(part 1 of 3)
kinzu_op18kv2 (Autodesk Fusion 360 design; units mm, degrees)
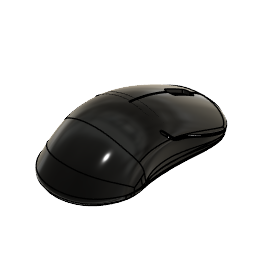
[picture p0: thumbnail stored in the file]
parameter "d11" = 0.5
parameter "d441" = 0.2
place_component sketch "スケッチ1"
sketch "スケッチ1" plane through (0, 0, 0) normal (0, 0, 1) x axis (1, 0, 0)
  line L1 (-100, -100) -> (100, -100)
  line L2 (-100, 100) -> (-100, -100)
  line L3 (100, 100) -> (-100, 100)
  line L4 (100, -100) -> (100, 100)
  line L5 (-100, 100) -> (100, -100)
  line L6 (100, 100) -> (-100, -100)
  point P6 (0, 0)
  point P1 (0, 0)
  point P4 (-100, 100)
  point P5 (100, 100)
  point P3 (-100, -100)
  horizontal L1
  perpendicular L1 L2
  parallel L1 L3
  parallel L2 L4
  coincident L5 P6
  coincident L6 P6
  coincident P1 P6
  dimension "d13" distance P4 P5 = 200
  dimension "d14" distance P3 P4 = 200
extrude "押し出し1" new body sketch "スケッチ1" profile of L1 L2 L3 L4 against normal blind 5
sketch "スケッチ1" plane through (0, 0, 0) normal (0, 0, 1) x axis (1, 0, 0)
  line L1 (2, 0) -> (-2, 0)
  line L2 (2, -4) -> (2, 0)
  line L3 (-2, -4) -> (2, -4)
  line L4 (-2, 0) -> (-2, -4)
  line L5 (0, -7.68) -> (0, 0)
  line L6 (4.05, 8.27) -> (-4.05, 8.27)
  line L7 (4.05, -7.68) -> (4.05, 8.27)
  line L8 (-4.05, -7.68) -> (4.05, -7.68)
  line L9 (-4.05, 8.27) -> (-4.05, -7.68)
  arc A1 centre (0, 0) radius 2 clockwise from (-2, 0) to (2, 0)
  point P7 (0, -7.68)
  point P6 (0, 0)
  point P12 (0, 0)
  point P2 (-2, 0)
  point P3 (2, 0)
  point P5 (-2, -4)
  point P8 (-4.05, 8.27)
  point P9 (4.05, 8.27)
  point P11 (-4.05, -7.68)
  horizontal L1
  vertical L2
  horizontal L3
  vertical L4
  perpendicular L3 L5
  horizontal L6
  vertical L7
  horizontal L8
  vertical L9
  midpoint P7 L8
  coincident P6 P12
  dimension "d2" distance P2 P3 = 4
  dimension "d3" distance P2 P5 = 4
  dimension "d4" distance P6 P7 = 7.68
  dimension "d5" distance P8 P9 = 8.1
  dimension "d6" distance P8 P11 = 15.95
  dimension "d21" radius A1 = 2
extrude "押し出し2" new body sketch "スケッチ1" profile of L1 L2 L3 L4 L5 A1 along normal blind 2.4 taper 22.5 bodies "lens"
extrude "押し出し5" add sketch "スケッチ1" to an object from offset 7.4
sketch "スケッチ1" plane through (0, 0, 0) normal (0, 0, 1) x axis (1, 0, 0)
  line L1 (-10, -10) -> (10, -10)
  line L2 (-10, 10) -> (-10, -10)
  line L3 (10, 10) -> (-10, 10)
  line L4 (10, -10) -> (10, 10)
  line L5 (-10, 10) -> (10, -10)
  line L6 (10, 10) -> (-10, -10)
  line L7 (2, -4) -> (2, 0)
  line L8 (-2, -4) -> (2, -4)
  line L9 (-2, 0) -> (-2, -4)
  line L10 (3.5, -4.5) -> (3.5, 0)
  line L11 (-2.5, -5.5) -> (2.5, -5.5)
  line L12 (-3.5, 0) -> (-3.5, -4.5)
  line L13 (-6.5, 0) -> (-6.5, -4.5)
  line L14 (6.5, -4.5) -> (6.5, 0)
  line L15 (-2.5, -8.5) -> (2.5, -8.5)
  arc A1 centre (0, 0) radius 2 clockwise from (-2, 0) to (2, 0)
  arc A2 centre (0, 0) radius 3.5 clockwise from (-3.5, 0) to (3.5, 0)
  arc A3 centre (-2.5, -4.5) radius 1 clockwise from (-2.5, -5.5) to (-3.5, -4.5)
  arc A4 centre (2.5, -4.5) radius 1 clockwise from (3.5, -4.5) to (2.5, -5.5)
  arc A5 centre (0, 0) radius 6.5 clockwise from (-6.5, 0) to (6.5, 0)
  arc A6 centre (2.5, -4.5) radius 4 clockwise from (6.5, -4.5) to (2.5, -8.5)
  arc A7 centre (-2.5, -4.5) radius 4 clockwise from (-2.5, -8.5) to (-6.5, -4.5)
  point P6 (0, 0)
  point P1 (0, 0)
  point P7 (0, 0)
  point P4 (-10, 10)
  point P5 (10, 10)
  point P3 (-10, -10)
  point P9 (-2, 0)
  point P10 (2, 0)
  point P12 (-2, -4)
  horizontal L1
  perpendicular L1 L2
  parallel L1 L3
  parallel L2 L4
  coincident L5 P6
  coincident L6 P6
  coincident P1 P6
  coincident P1 P7
  vertical L7
  horizontal L8
  vertical L9
  concentric A1 A2
  tangent L12 A2
  tangent L12 A3
  tangent L11 A3
  tangent L10 A4
  tangent L11 A4
  equal A3 A4
  dimension "d29" distance P4 P5 = 20
  dimension "d30" distance P3 P4 = 20
  dimension "d40" radius A1 = 2
  dimension "d41" distance P9 P10 = 4
  dimension "d42" distance P9 P12 = 4
  dimension "d44" radius A3 = 1
  dimension "d45" = 3
extrude "押し出し2" sketch "スケッチ1" profile of L1 L2 L3 L4 A1 L7 L8 L9 L10 L11 L12 A2 A3 A4 L13 A7 L14 A5 A6 L15 to an object offset 0.5 from offset -0.5 bodies "around_lens"
extrude "押し出し3" cut sketch "スケッチ1" profile of L10 L11 L12 A2 A3 A4 L13 A7 L14 A5 A6 L15 along normal blind 0.7
combine "結合2"
sketch "スケッチ1" plane through (0, 0, 0) normal (0, 0, 1) x axis (1, 0, 0)
  line L1 (0, -15) -> (0, 15)
  line L2 (-5.25, -15) -> (-5.25, 15)
  line L3 (5.25, -15) -> (5.25, 15)
  line L4 (-4.3, -15) -> (-4.3, 15)
  line L5 (4.3, -15) -> (4.3, 15)
  line L6 (10, 0) -> (-10, 0)
  line L7 (10, -8.44) -> (-10, -8.44)
  line L8 (10, 8.82) -> (-10, 8.82)
  line L9 (10, -5.66) -> (-10, -5.66)
  line L10 (10, 6.8) -> (-10, 6.8)
  line L11 (10, 7.69) -> (-10, 7.69)
  line L12 (10, -4.77) -> (-10, -4.77)
  line L13 (5.45, -15) -> (5.45, 15)
  line L14 (-5.45, -15) -> (-5.45, 15)
  line L15 (10, 7.94) -> (-10, 7.94)
  line L16 (10, 7.05) -> (-10, 7.05)
  line L17 (10, -5.02) -> (-10, -5.02)
  line L18 (10, -5.91) -> (-10, -5.91)
  point P1 (0, 0)
  vertical L1
  midpoint P1 L1
  perpendicular L2 L6
  midpoint P1 L6
  dimension "d91" = 5.25
  dimension "d92" = -5.25
  dimension "d93" = 4.3
  dimension "d94" = -4.3
  dimension "d95" = 8.44
  dimension "d96" = -8.82
  dimension "d97" = 5.66
  dimension "d102" = -12.46 (= "( -1.78 * 7 ) * 1 mm")
  dimension "d103" = -0.89
  dimension "d104" = -0.89
  dimension "d105" = -0.2
  dimension "d106" = 0.2
  dimension "d107" = -0.25
  dimension "d108" = -0.25
  dimension "d109" = 0.25
  dimension "d110" = 0.25
extrude "押し出し1" new body sketch "スケッチ1" profile of L1 L4 L5 L6 L7 L8 L9 L10 L11 L12 L15 L16 L17 L18 to an object offset 7.4 from offset 9.81 bodies "sensor"
extrude "押し出し2" sketch "スケッチ1" profile of L2 L3 L4 L5 L6 L9 L10 L11 L12 L13 L14 L15 L16 L17 L18 blind -0.2 from offset -0.5
extrude "押し出し3" sketch "スケッチ1" profile of L2 L3 L6 L9 L10 L11 L12 L13 L14 L15 L16 L17 L18 blind -4.51 from offset -0.5
sketch "スケッチ1" plane through (0, 0, 0) normal (0, 0, 1) x axis (1, 0, 0)
  line L1 (0, 15.4) -> (0, 0)
  line L2 (0, -14.4) -> (0, 0)
  line L3 (-4.3, 0) -> (4.3, 0)
  line L4 (-4.3, 8.82) -> (4.3, 8.82)
  line L5 (-4.3, -8.44) -> (4.3, -8.44)
  line L6 (4.3, 8.82) -> (4.3, -8.44)
  line L7 (-4.3, 8.82) -> (-4.3, -8.44)
  line L8 (12, 15.4) -> (0, 15.4)
  line L9 (-12.8, 15.4) -> (0, 15.4)
  line L10 (0, -31.8) -> (0, 0)
  circle C1 centre (12, 15.4) radius 1.4
  circle C2 centre (-12.8, 15.4) radius 1.4
  circle C3 centre (0, -14.4) radius 1.4
  circle C4 centre (0, -31.8) radius 1.4
  point P1 (0, 0)
  point P2 (0, 0)
  point P6 (0, 0)
  point P7 (0, -14.4)
  point P8 (0, -14.4)
  point P4 (12, 15.4)
  point P16 (12, 15.4)
  point P5 (-12.8, 15.4)
  point P17 (-12.8, 15.4)
  point P18 (0, 0)
  point P9 (0, -31.8)
  point P19 (0, -31.8)
  point P3 (0, 15.4)
  point P10 (4.3, 0)
  point P11 (-4.3, 0)
  coincident P1 P2
  vertical L1
  coincident P1 P6
  coincident P7 P8
  perpendicular L2 L3
  midpoint P6 L3
  perpendicular L4 L6
  perpendicular L4 L7
  perpendicular L1 L8
  perpendicular L1 L9
  coincident P4 P16
  coincident P5 P17
  coincident P1 P18
  perpendicular L3 L10
  coincident P9 P19
  dimension "d51" distance P2 P3 = 15.4
  dimension "d53" diameter C1 = 2.8
  dimension "d54" diameter C2 = 2.8
  dimension "d56" distance P6 P7 = 14.4
  dimension "d57" diameter C3 = 2.8
  dimension "d58" diameter C4 = 2.8
  dimension "d120" distance P10 P11 = 8.6
  dimension "d121" = 8.82
  dimension "d122" = -8.44
  dimension "d187" distance P3 P16 = 12
  dimension "d188" distance P3 P17 = 12.8
  dimension "d189" distance P18 P19 = 31.8
sketch "スケッチ2" plane through (0, 0, 0) normal (0, 0, 1) x axis (1, 0, 0)
  line L1 (50, 0) -> (-50, 0)
  line L2 (0, -50) -> (0, 50)
  line L3 (-13.8, -50) -> (-13.8, 50)
  line L4 (14, -50) -> (14, 50)
  line L5 (50, 39.3) -> (-50, 39.3)
  line L6 (50, -12.8) -> (-50, -12.8)
  line L7 (50, -33.6) -> (-50, -33.6)
  line L8 (-2.3, -50) -> (-2.3, 50)
  line L9 (2.3, -50) -> (2.3, 50)
  line L10 (7.3, -50) -> (7.3, 50)
  line L11 (50, -28.4) -> (-50, -28.4)
  line L12 (50, -9.7) -> (-50, -9.7)
  line L13 (-10.1, -50) -> (-10.1, 50)
  line L14 (9.3, -50) -> (9.3, 50)
  line L15 (50, -7.7) -> (-50, -7.7)
  line L16 (50, 36.5) -> (-50, 36.5)
  line L17 (-7.3, 39.3) -> (-10.1, 36.5)
  line L18 (10.6, -50) -> (10.6, 50)
  line L19 (14, 20.0176) -> (10.6, 39.3)
  point P1 (0, 0)
  point P34 (-10.1, 36.5)
  point P35 (-7.3, 39.3)
  point P38 (10.6, 39.3)
  point P39 (14, 20.0176)
  horizontal L1
  midpoint P1 L1
  vertical L2
  midpoint P1 L2
  coincident L13 P34
  coincident L16 P34
  coincident L5 P35
  coincident L18 P38
  coincident L5 P38
  coincident L4 P39
  dimension "d73" = 13.8
  dimension "d74" = -14
  dimension "d75" = -39.3
  dimension "d76" = 12.8
  dimension "d77" = 20.8
  dimension "d78" = 2.3
  dimension "d79" = -2.3
  dimension "d80" = -5
  dimension "d81" = -5.2
  dimension "d82" = -3.1
  dimension "d83" = -3.7
  dimension "d205" = 4.7
  dimension "d206" = -5.1
  dimension "d211" = -36.5
  dimension "d212" angle L5 L17 = 45
  dimension "d214" = 3.4
  dimension "d416" angle L5 L19 = 80
sketch "スケッチ3" plane through (0, 0, 0) normal (0, 0, 1) x axis (1, 0, 0)
  line L1 (25, 0) -> (-25, 0)
  line L2 (25, 22.2) -> (-25, 22.2)
  line L3 (25, 37.6) -> (-25, 37.6)
  line L4 (0, 50.6) -> (0, 0)
  line L5 (6.8, 50.6) -> (6.8, 0.6)
  line L6 (-6.8, 50.6) -> (-6.8, 0.6)
  line L7 (25, 36) -> (-25, 36)
  line L8 (25, 34.2) -> (-25, 34.2)
  line L9 (25, 23.1) -> (-25, 23.1)
  line L10 (25, 24.9) -> (-25, 24.9)
  line L11 (7.6, 50.6) -> (7.6, 0.6)
  line L12 (-7.6, 50.6) -> (-7.6, 0.6)
  circle C1 centre (-4.8, 35.6) radius 2
  circle C2 centre (-5.3, 23.7) radius 1.5
  circle C3 centre (5.6, 35.6) radius 2
  circle C4 centre (4.8, 24.2) radius 2
  point P1 (0, 0)
  point P8 (0, 0)
  horizontal L1
  coincident P1 P8
  perpendicular L3 L4
  tangent L6 C1
  tangent L3 C1
  tangent L2 C2
  tangent L6 C2
  tangent L3 C3
  tangent L11 C3
  tangent L5 C4
  tangent L2 C4
  dimension "d156" = -22.2
  dimension "d157" = -15.4
  dimension "d158" = 6.8
  dimension "d159" = -6.8
  dimension "d169" = 1.6
  dimension "d170" = 1.8
  dimension "d171" = -0.9
  dimension "d172" = -1.8
  dimension "d174" = 0.8
  dimension "d175" radius C1 = 2
  dimension "d176" radius C2 = 1.5
  dimension "d177" = -0.8
  dimension "d178" radius C3 = 2
  dimension "d179" radius C4 = 2
extrude "押し出し1" new body sketch "スケッチ2" blind -0.8 from offset 7.4 bodies "main_pcb"
extrude "押し出し2" cut sketch "スケッチ1" profile of L1 C1 C2 L2 C3 C4 L3 L4 L5 L6 L7 to an object
extrude "押し出し3" sketch "スケッチ3" profile of L2 L3 L4 L5 L6 L7 L8 L9 L10 L11 C1 C2 L12 C3 C4 to an object
sketch "スケッチ5" plane through (0, 0, 0) normal (0, 0, 1) x axis (1, 0, 0)
  line L1 (-12.25, 0) -> (0, 0)
  line L2 (-12.25, -5.5) -> (-12.25, 0)
  line L3 (0, -5.5) -> (-12.25, -5.5)
  line L4 (0, 0) -> (0, -5.5)
  line L5 (-11.45, 0) -> (0, 0)
  line L6 (-11.45, 9.05) -> (-11.45, 0)
  line L7 (0, 9.05) -> (-11.45, 9.05)
  line L8 (0, 0) -> (0, 9.05)
  line L9 (10.7, 0) -> (0, 0)
  line L10 (10.7, -2.8) -> (10.7, 0)
  line L11 (0, -2.8) -> (10.7, -2.8)
  line L12 (0, 0) -> (0, -2.8)
  line L13 (12.2, 0) -> (0, 0)
  line L14 (12.2, 9.05) -> (12.2, 0)
  line L15 (0, 9.05) -> (12.2, 9.05)
  line L16 (0, 0) -> (0, 9.05)
  line L17 (-12.5, -7.75) -> (-12.5, -3.25)
  line L18 (-12, -3.25) -> (-12, -7.75)
  line L19 (-12.25, -7.75) -> (-12.25, -3.25)
  line L20 (10.45, -5.8) -> (10.45, 0.2)
  line L21 (10.95, 0.2) -> (10.95, -5.8)
  line L22 (10.7, -5.8) -> (10.7, 0.2)
  line L23 (11.95, 7.55) -> (11.95, 10.55)
  line L24 (12.45, 10.55) -> (12.45, 7.55)
  line L25 (12.2, 7.55) -> (12.2, 10.55)
  line L26 (-11.7, 7.55) -> (-11.7, 10.55)
  line L27 (-11.2, 10.55) -> (-11.2, 7.55)
  line L28 (-11.45, 7.55) -> (-11.45, 10.55)
  line L29 (-13.8, -9.25) -> (-10.2, -9.25)
  line L30 (-13.8, -1.75) -> (-13.8, -9.25)
  line L31 (-10.2, -1.75) -> (-13.8, -1.75)
  line L32 (-10.2, -9.25) -> (-10.2, -1.75)
  line L33 (-13.8, -1.75) -> (-10.2, -9.25)
  line L34 (-10.2, -1.75) -> (-13.8, -9.25)
  line L35 (-13.5, 6.05) -> (-9.9, 6.05)
  line L36 (-13.5, 12.05) -> (-13.5, 6.05)
  line L37 (-9.9, 12.05) -> (-13.5, 12.05)
  line L38 (-9.9, 6.05) -> (-9.9, 12.05)
  line L39 (-13.5, 12.05) -> (-9.9, 6.05)
  line L40 (-9.9, 12.05) -> (-13.5, 6.05)
  line L41 (10.15, 6.05) -> (13.75, 6.05)
  line L42 (10.15, 12.05) -> (10.15, 6.05)
  line L43 (13.75, 12.05) -> (10.15, 12.05)
  line L44 (13.75, 6.05) -> (13.75, 12.05)
  line L45 (10.15, 12.05) -> (13.75, 6.05)
  line L46 (13.75, 12.05) -> (10.15, 6.05)
  line L47 (15.45, 1.7) -> (10.45, 1.7)
  line L48 (15.45, -7.3) -> (15.45, 1.7)
  line L49 (10.45, -7.3) -> (15.45, -7.3)
  line L50 (10.45, 1.7) -> (10.45, -7.3)
  line L51 (-12.95, 0) -> (0, 0)
  line L52 (-12.95, 20.2) -> (-12.95, 0)
  line L53 (0, 20.2) -> (-12.95, 20.2)
  line L54 (0, 0) -> (0, 20.2)
  line L55 (-11.9, 19.15) -> (-14, 19.15)
  line L56 (-11.9, 21.25) -> (-11.9, 19.15)
  line L57 (-14, 21.25) -> (-11.9, 21.25)
  line L58 (-14, 19.15) -> (-14, 21.25)
  line L59 (-11.9, 21.25) -> (-14, 19.15)
  line L60 (-14, 21.25) -> (-11.9, 19.15)
  line L61 (5.35, 0) -> (0, 0)
  line L62 (5.35, -24.1) -> (5.35, 0)
  line L63 (0, -24.1) -> (5.35, -24.1)
  line L64 (0, 0) -> (0, -24.1)
  line L65 (3.65, -25.8) -> (7.05, -25.8)
  line L66 (3.65, -22.4) -> (3.65, -25.8)
  line L67 (7.05, -22.4) -> (3.65, -22.4)
  line L68 (7.05, -25.8) -> (7.05, -22.4)
  line L69 (3.65, -22.4) -> (7.05, -25.8)
  line L70 (7.05, -22.4) -> (3.65, -25.8)
  line L71 (5.263, 34.1334) -> (10.2639, 35.0265)
  line L72 (7.5133, 21.5328) -> (5.263, 34.1334)
  line L73 (12.5142, 22.4259) -> (7.5133, 21.5328)
  line L74 (10.2639, 35.0265) -> (12.5142, 22.4259)
  line L75 (7.5133, 21.5328) -> (10.2639, 35.0265)
  line L76 (12.5142, 22.4259) -> (5.263, 34.1334)
  line L77 (8.0065, 33.2824) -> (9.7707, 23.2768)
  line L78 (8.55, 30.2) -> (8.8886, 28.2796)
  line L79 (7.2262, 29.3573) -> (10.0822, 29.8609)
  line L80 (7.0178, 30.5391) -> (7.2262, 29.3573)
  line L81 (9.8738, 31.0427) -> (7.0178, 30.5391)
  line L82 (10.0822, 29.8609) -> (9.8738, 31.0427)
  line L83 (7.0178, 30.5391) -> (10.0822, 29.8609)
  line L84 (9.8738, 31.0427) -> (7.2262, 29.3573)
  line L85 (9.6519, 22.7989) -> (10.0458, 22.8684)
  line L86 (7.7314, 33.6909) -> (9.6519, 22.7989)
  line L87 (8.1253, 33.7603) -> (7.7314, 33.6909)
  line L88 (10.0458, 22.8684) -> (8.1253, 33.7603)
  line L89 (7.7314, 33.6909) -> (10.0458, 22.8684)
  line L90 (8.1253, 33.7603) -> (9.6519, 22.7989)
  line L91 (8.55, 0) -> (0, 0)
  line L92 (8.55, 30.2) -> (8.55, 0)
  line L93 (0, 30.2) -> (8.55, 30.2)
  line L94 (0, 0) -> (0, 30.2)
  arc A1 centre (-12.25, -7.75) radius 0.25 clockwise from (-12, -7.75) to (-12.5, -7.75)
  arc A2 centre (-12.25, -3.25) radius 0.25 clockwise from (-12.5, -3.25) to (-12, -3.25)
  arc A3 centre (10.7, -5.8) radius 0.25 clockwise from (10.95, -5.8) to (10.45, -5.8)
  arc A4 centre (10.7, 0.2) radius 0.25 clockwise from (10.45, 0.2) to (10.95, 0.2)
  arc A5 centre (12.2, 7.55) radius 0.25 clockwise from (12.45, 7.55) to (11.95, 7.55)
  arc A6 centre (12.2, 10.55) radius 0.25 clockwise from (11.95, 10.55) to (12.45, 10.55)
  arc A7 centre (-11.45, 7.55) radius 0.25 clockwise from (-11.2, 7.55) to (-11.7, 7.55)
  arc A8 centre (-11.45, 10.55) radius 0.25 clockwise from (-11.7, 10.55) to (-11.2, 10.55)
  circle C1 centre (5.35, -24.1) radius 0.85
  point P1 (0, 0)
  point P2 (0, 0)
  point P6 (0, 0)
  point P10 (0, 0)
  point P14 (0, 0)
  point P4 (-12.25, -5.5)
  point P24 (-12.25, -5.5)
  point P12 (10.7, -2.8)
  point P31 (10.7, -2.8)
  point P16 (12.2, 9.05)
  point P38 (12.2, 9.05)
  point P8 (-11.45, 9.05)
  point P45 (-11.45, 9.05)
  point P50 (-12, -5.5)
  point P55 (-11.7, 9.05)
  point P60 (11.95, 9.05)
  point P65 (0, 0)
  point P73 (-12.95, 20.2)
  point P67 (-12.95, 20.2)
  point P74 (0, 0)
  point P82 (5.35, -24.1)
  point P76 (5.35, -24.1)
  point P83 (5.35, -24.1)
  point P88 (8.8886, 28.2796)
  point P91 (8.8886, 28.2796)
  point P92 (8.8886, 28.2796)
  point P98 (8.55, 30.2)
  point P93 (8.55, 30.2)
  point P103 (8.8886, 28.2796)
  point P104 (0, 0)
  point P106 (8.55, 30.2)
  point P3 (-12.25, 0)
  point P5 (0, -5.5)
  point P7 (-11.45, 0)
  point P9 (0, 9.05)
  point P11 (10.7, 0)
  point P13 (0, -2.8)
  point P15 (12.2, 0)
  point P17 (0, 9.05)
  point P48 (-13.8, -1.75)
  point P49 (-10.2, -1.75)
  point P47 (-13.8, -9.25)
  point P53 (-13.5, 12.05)
  point P54 (-9.9, 12.05)
  point P52 (-13.5, 6.05)
  point P58 (10.15, 12.05)
  point P59 (13.75, 12.05)
  point P57 (10.15, 6.05)
  point P61 (10.45, 1.7)
  point P62 (15.45, 1.7)
  point P64 (10.45, -7.3)
  point P66 (-12.95, 0)
  point P68 (0, 20.2)
  point P71 (-11.9, 21.25)
  point P72 (-14, 21.25)
  point P70 (-11.9, 19.15)
  point P75 (5.35, 0)
  point P77 (0, -24.1)
  point P80 (3.65, -22.4)
  point P81 (7.05, -22.4)
  point P79 (3.65, -25.8)
  point P86 (7.5133, 21.5328)
  point P87 (12.5142, 22.4259)
  point P85 (5.263, 34.1334)
  point P90 (8.0065, 33.2824)
  point P96 (7.0178, 30.5391)
  point P97 (9.8738, 31.0427)
  point P95 (7.2262, 29.3573)
  point P101 (7.7314, 33.6909)
  point P102 (8.1253, 33.7603)
  point P100 (9.6519, 22.7989)
  point P105 (8.55, 0)
  point P107 (0, 30.2)
  horizontal L1
  vertical L2
  horizontal L3
  vertical L4
  coincident P1 P2
  horizontal L5
  vertical L6
  horizontal L7
  vertical L8
  coincident P1 P6
  horizontal L9
  vertical L10
  horizontal L11
  vertical L12
  coincident P1 P10
  horizontal L13
  vertical L14
  horizontal L15
  vertical L16
  coincident P1 P14
  tangent L17 A1
  tangent A1 L18
  parallel L17 L18
  tangent L18 A2
  tangent L17 A2
  perpendicular L3 L19
  coincident P4 P24
  midpoint L19 P24
  tangent L20 A3
  tangent A3 L21
  parallel L20 L21
  tangent L21 A4
  tangent L20 A4
  perpendicular L11 L22
  coincident P12 P31
  midpoint L22 P31
  tangent L23 A5
  tangent A5 L24
  parallel L23 L24
  tangent L24 A6
  tangent L23 A6
  perpendicular L15 L25
  coincident P16 P38
  midpoint L25 P38
  tangent L26 A7
  tangent A7 L27
  parallel L26 L27
  tangent L27 A8
  tangent L26 A8
  perpendicular L7 L28
  coincident P8 P45
  midpoint L28 P45
  horizontal L29
  perpendicular L29 L30
  parallel L29 L31
  parallel L30 L32
  coincident L33 P50
  coincident L34 P50
  horizontal L35
  perpendicular L35 L36
  parallel L35 L37
  parallel L36 L38
  coincident L39 P55
  coincident L40 P55
  midpoint L26 P55
  horizontal L41
  perpendicular L41 L42
  parallel L41 L43
  parallel L42 L44
  coincident L45 P60
  coincident L46 P60
  horizontal L47
  vertical L48
  horizontal L49
  vertical L50
  midpoint L20 L50
  midpoint L18 P50
  midpoint L23 P60
  horizontal L51
  vertical L52
  horizontal L53
  vertical L54
  coincident P1 P65
  horizontal L55
  perpendicular L55 L56
  parallel L55 L57
  parallel L56 L58
  coincident L59 P73
  coincident L60 P73
  coincident P67 P73
  horizontal L61
  vertical L62
  horizontal L63
  vertical L64
  coincident P1 P74
  horizontal L65
  perpendicular L65 L66
  parallel L65 L67
  parallel L66 L68
  coincident L69 P82
  coincident L70 P82
  coincident P76 P82
  coincident P82 P83
  perpendicular L71 L72
  parallel L71 L73
  parallel L72 L74
  coincident L75 P88
  coincident L76 P88
  coincident P88 P91
  midpoint L77 P91
  coincident P88 P92
  parallel L77 L78
  perpendicular L79 L80
  parallel L79 L81
  parallel L80 L82
  coincident L83 P98
  coincident L84 P98
  coincident P93 P98
  parallel L77 L82
  perpendicular L85 L86
  parallel L85 L87
  parallel L86 L88
  coincident L89 P103
  coincident L90 P103
  coincident P88 P103
  parallel L77 L88
  horizontal L91
  vertical L92
  horizontal L93
  vertical L94
  coincident P1 P104
  coincident P98 P106
  dimension "d218" distance P2 P3 = 12.25
  dimension "d219" distance P2 P5 = 5.5
  dimension "d220" distance P6 P7 = 11.45
  dimension "d221" distance P6 P9 = 9.05
  dimension "d222" distance P10 P11 = 10.7
  dimension "d223" distance P10 P13 = 2.8
  dimension "d224" distance P14 P15 = 12.2
  dimension "d225" distance P14 P17 = 9.05
  dimension "d226" diameter A1 = 0.5
  dimension "d227" diameter A3 = 0.5
  dimension "d228" diameter A5 = 0.5
  dimension "d229" diameter A7 = 0.5
  dimension "d230" distance P48 P49 = 3.6
  dimension "d231" distance P47 P48 = 7.5
  dimension "d232" distance P53 P54 = 3.6
  dimension "d233" distance P52 P53 = 6
  dimension "d234" distance P58 P59 = 3.6
  dimension "d235" distance P57 P58 = 6
  dimension "d236" distance P61 P62 = 5
  dimension "d237" distance P61 P64 = 9
  dimension "d255" distance P65 P66 = 12.95
  dimension "d256" distance P65 P68 = 20.2
  dimension "d257" distance P71 P72 = 2.1
  dimension "d258" distance P70 P71 = 2.1
  dimension "d259" distance P74 P75 = 5.35
  dimension "d260" distance P74 P77 = 24.1
  dimension "d261" distance P80 P81 = 3.4
  dimension "d262" distance P79 P80 = 3.4
  dimension "d266" diameter C1 = 1.7
  dimension "d276" distance P86 P87 = 5.08
  dimension "d277" distance P85 P86 = 12.8
  dimension "d280" distance P90 P91 = 5.08
  dimension "d294" distance P92 P93 = 1.95
  dimension "d295" distance P96 P97 = 2.9
  dimension "d296" distance P95 P96 = 1.2
  dimension "d337" distance P101 P102 = 0.4
  dimension "d338" distance P100 P101 = 11.06 (= "( 5.53 * 2 ) * 1 mm")
  dimension "d369" distance P104 P105 = 8.55
  dimension "d370" distance P104 P107 = 30.2
  dimension "d415" angle L77 L93 = 80
extrude "押し出し4" sketch "スケッチ5" profile of L2 L3 L6 L7 L9 L10 L11 L13 L14 L15 L17 A1 L18 A2 L20 A3 L21 A4 L23 A5 L24 A6 L26 A7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 blind 5 bodies "zh_rmb", "zh_usb", "zh_lmb", "zh_side"
extrude "押し出し5" sketch "スケッチ5" profile of L2 L3 L6 L7 L9 L10 L11 L13 L14 L15 L17 A1 L18 A2 L20 A3 L21 A4 L23 A5 L24 A6 L26 A7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 blind -3
extrude "押し出し6" sketch "スケッチ5" profile of L52 L53 L55 L56 L57 L58 L62 L63 L65 L66 L67 L68 blind -1 bodies "LED", "dpi_sw"
extrude "押し出し7" sketch "スケッチ5" profile of L62 L63 C1 blind -0.7
extrude "押し出し8" sketch "スケッチ5" profile of L78 L79 L81 L85 L86 L87 L88 blind -3.2 bodies "whl_sw"
extrude "押し出し9" sketch "スケッチ5" profile of L71 L72 L73 L74 L78 L79 L80 L81 L82 blind 6.5
extrude "押し出し10" sketch "スケッチ5" profile of L79 L80 L81 L82 blind 0.85
sketch "スケッチ6" plane through (0, 0, 0) normal (1, 0, 0) x axis (0, 1, 0)
  line L1 (30.2, 0) -> (0, 0)
  line L2 (30.2, 7.4) -> (30.2, 0)
  line L3 (0, 7.4) -> (30.2, 7.4)
  line L4 (0, 0) -> (0, 7.4)
  line L5 (27.2, 7.4) -> (33.2, 7.4)
  line L6 (27.2, 3.9) -> (27.2, 7.4)
  line L7 (33.2, 3.9) -> (27.2, 3.9)
  line L8 (33.2, 7.4) -> (33.2, 3.9)
  line L9 (30.15, 20) -> (30.25, 20)
  line L10 (25.3, 7.4) -> (25.3, 20)
  line L11 (35.1, 7.4) -> (25.3, 7.4)
  line L12 (35.1, 20) -> (35.1, 7.4)
  line L13 (24.3, 7.4) -> (25.3, 7.4)
  line L14 (24.3, 3.9) -> (24.3, 7.4)
  line L15 (25.3, 3.9) -> (24.3, 3.9)
  line L16 (25.3, 7.4) -> (25.3, 3.9)
  line L17 (24.3, 5.65) -> (25.3, 7.4)
  line L18 (24.3, 5.65) -> (25.3, 3.9)
  line L19 (24.8759, 5.65) -> (25.7341, 7.1519)
  line L20 (24.8759, 5.65) -> (25.7341, 4.1481)
  line L21 (25.3, 3.9) -> (25.7341, 4.1481)
  line L22 (25.7341, 7.4) -> (25.7341, 7.1519)
  line L23 (35.1, 3.9) -> (34.6659, 4.1481)
  line L24 (36.1, 5.65) -> (35.1, 3.9)
  line L25 (35.5241, 5.65) -> (34.6659, 7.1519)
  line L26 (35.5241, 5.65) -> (34.6659, 4.1481)
  line L27 (34.6659, 7.4) -> (34.6659, 7.1519)
  line L28 (36.1, 5.65) -> (35.1, 7.4)
  line L29 (30.2, 16.4) -> (30.2, 7.4)
  line L30 (30.2, 15.4012) -> (29.335, 15.9006)
  line L31 (31.065, 15.9006) -> (30.2, 15.4012)
  line L32 (31.065, 16.8994) -> (31.065, 15.9006)
  line L33 (30.2, 17.3988) -> (31.065, 16.8994)
  line L34 (29.335, 16.8994) -> (30.2, 17.3988)
  line L35 (29.335, 15.9006) -> (29.335, 16.8994)
  line L36 (30.2, 20) -> (30.2, 17.3988)
  line L37 (28.0851, 19.3489) -> (25.3, 17.3988)
  line L38 (32.3149, 19.3489) -> (35.1, 17.3988)
  arc A1 centre (30.15, 16.4) radius 3.6 clockwise from (28.0851, 19.3489) to (30.15, 20)
  arc A2 centre (30.25, 16.4) radius 3.6 clockwise from (30.25, 20) to (32.3149, 19.3489)
  point P1 (0, 0)
  point P2 (0, 0)
  point P17 (24.3, 5.65)
  point P4 (30.2, 7.4)
  point P21 (25.7341, 7.4)
  point P12 (25.3, 7.4)
  point P27 (35.1, 7.4)
  point P16 (25.3, 3.9)
  point P23 (35.1, 3.9)
  point P28 (36.1, 5.65)
  point P18 (25.7341, 7.1519)
  point P24 (34.6659, 7.1519)
  point P19 (24.8759, 5.65)
  point P26 (35.5241, 5.65)
  point P20 (25.7341, 4.1481)
  point P25 (34.6659, 4.1481)
  point P22 (34.6659, 7.4)
  point P29 (30.2, 16.4)
  point P36 (30.2, 16.4)
  point P38 (25.3, 17.3988)
  point P39 (35.1, 17.3988)
  point P37 (30.2, 20)
  point P11 (25.3, 20)
  point P10 (35.1, 20)
  point P3 (30.2, 0)
  point P5 (0, 7.4)
  point P6 (33.2, 7.4)
  point P7 (27.2, 7.4)
  point P9 (33.2, 3.9)
  point P13 (35.1, 7.4)
  point P14 (24.3, 7.4)
  horizontal L1
  vertical L2
  horizontal L3
  vertical L4
  coincident P1 P2
  horizontal L5
  vertical L6
  horizontal L7
  vertical L8
  horizontal L9
  vertical L10
  horizontal L11
  vertical L12
  horizontal L13
  vertical L14
  horizontal L15
  vertical L16
  midpoint L14 P17
  perpendicular L18 L21
  midpoint P4 L5
  midpoint P4 L11
  perpendicular L11 L22
  coincident L3 P21
  symmetric L2 P12 P27
  symmetric L2 P16 P23
  symmetric L2 P17 P28
  symmetric L2 P18 P24
  symmetric L2 P19 P26
  symmetric L2 P20 P25
  symmetric L2 P21 P22
  perpendicular L3 L29
  coincident P29 P36
  perpendicular L9 L36
  coincident L10 P38
  symmetric L2 P38 P39
  coincident L9 P37
  coincident P11 L9
  tangent L37 A1
  tangent L9 A1
  coincident P10 L9
  tangent L38 A2
  tangent L9 A2
  equal A1 A2
  dimension "d340" distance P2 P3 = 30.2
  dimension "d341" distance P2 P5 = 7.4
  dimension "d342" distance P6 P7 = 6
  dimension "d343" distance P6 P9 = 3.5
  dimension "d344" distance P10 P11 = 9.8
  dimension "d345" distance P10 P13 = 12.6
  dimension "d348" distance P12 P14 = 1
  dimension "d349" distance P12 P16 = 3.5
  dimension "d352" = -0.5
  dimension "d353" distance P4 P29 = 9
  dimension "d354" distance P36 L35 = 0.865 (= "( 1.73 / 2 ) * 1 mm")
  dimension "d356" radius A1 = 3.6
extrude "押し出し13" new body sketch "スケッチ6" profile of L3 L5 L9 L10 L11 L12 L29 L30 L31 L32 L33 L34 L35 L36 L37 L38 A1 A2 blind 3 second side blind 1.4 from offset -11 bodies "whl_ec"
extrude "押し出し14" sketch "スケッチ6" profile of L3 L11 L16 L17 L18 L19 L20 L21 L22 L23 L24 L25 L26 L27 L28 blind 2 from offset -3
extrude "押し出し15" sketch "スケッチ6" profile of L2 L3 L5 L6 L7 L8 L11 blind 0.3 from offset -1
sketch "スケッチ1" plane through (0, 0, 0) normal (1, 0, 0) x axis (0, 1, 0)
  line L1 (0, 30) -> (0, 0)
  line L2 (30.2, 30) -> (30.2, 0)
  line L3 (40, 0) -> (0, 0)
  line L4 (40, 7.4) -> (0, 7.4)
  line L5 (40, 16.4) -> (0, 16.4)
  line L6 (30.2, 15.4012) -> (29.335, 15.9006)
  line L7 (31.065, 15.9006) -> (30.2, 15.4012)
  line L8 (31.065, 16.8994) -> (31.065, 15.9006)
  line L9 (30.2, 17.3988) -> (31.065, 16.8994)
  line L10 (29.335, 16.8994) -> (30.2, 17.3988)
  line L11 (29.335, 15.9006) -> (29.335, 16.8994)
  circle C1 centre (30.2, 16.4) radius 8.25
  circle C2 centre (30.2, 16.4) radius 9.4
  circle C3 centre (30.2, 16.4) radius 2.15
  circle C4 centre (30.2, 16.4) radius 1.8
  circle C5 centre (30.2, 16.4) radius 1.075
  circle C6 centre (30.2, 16.4) radius 10.675
  point P1 (0, 0)
  point P2 (0, 0)
  point P6 (0, 0)
  point P12 (30.2, 16.4)
  point P16 (30.2, 16.4)
  point P23 (30.2, 16.4)
  point P3 (0, 30)
  point P7 (40, 0)
  coincident P1 P2
  vertical L1
  coincident P1 P6
  perpendicular L2 L3
  coincident L2 P12
  coincident L5 P12
  concentric C1 C2
  concentric C2 C3
  concentric C1 C4
  concentric C4 C5
  coincident P16 P23
  concentric C5 C6
  dimension "d371" distance P2 P3 = 30
  dimension "d372" = 30.2
  dimension "d373" distance P6 P7 = 40
  dimension "d374" = -7.4
  dimension "d375" = -9
  dimension "d376" diameter C1 = 16.5
  dimension "d377" diameter C2 = 18.8
  dimension "d378" diameter C3 = 4.3
  dimension "d379" diameter C4 = 3.6
  dimension "d380" diameter C5 = 2.15
  dimension "d381" distance P23 L11 = 0.865 (= "( 1.73 / 2 ) * 1 mm")
  dimension "d394" diameter C6 = 21.35
extrude "押し出し1" new body sketch "スケッチ1" profile of L2 L4 L5 C1 C2 C3 C4 C5 L6 L7 L8 L9 L10 L11 distance 6.8 bodies "wheel"
extrude "押し出し2" cut sketch "スケッチ1" profile of L2 L4 L5 C1 C2 distance 5
extrude "押し出し3" add sketch "スケッチ1" profile of L2 L5 C3 C4 C5 L6 L7 L8 L9 L10 L11 distance 8.15
extrude "押し出し4" add sketch "スケッチ1" profile of L2 L5 L6 L7 L8 L9 L10 L11 against normal blind 10.6
extrude "押し出し5" add sketch "スケッチ1" profile of L2 L5 C5 L6 L7 L8 L9 L10 L11 against normal blind 5.7
extrude "押し出し6" add sketch "スケッチ1" profile of L2 L5 C4 C5 L6 L7 L8 L9 L10 L11 along normal blind 10.4
extrude "押し出し7" new body sketch "スケッチ1" profile of L2 L4 L5 C1 C2 C6 distance 5 bodies "wheel_ring"
sketch "スケッチ1" plane through (0, 0, 0) normal (0, 0, 1) x axis (1, 0, 0)
  line L1 (-22.9, 36.4) -> (-17.1, 36.4)
  line L2 (-22.9, 23.6) -> (-22.9, 36.4)
  line L3 (-17.1, 23.6) -> (-22.9, 23.6)
  line L4 (-17.1, 36.4) -> (-17.1, 23.6)
  line L5 (-22.9, 23.6) -> (-17.1, 36.4)
  line L6 (-17.1, 23.6) -> (-22.9, 36.4)
  line L7 (-20.2, 24.47) -> (-19.8, 24.47)
  line L8 (-20.2, 35.53) -> (-20.2, 24.47)
  line L9 (-19.8, 35.53) -> (-20.2, 35.53)
  line L10 (-19.8, 24.47) -> (-19.8, 35.53)
  line L11 (-20.2, 35.53) -> (-19.8, 24.47)
  line L12 (-19.8, 35.53) -> (-20.2, 24.47)
  line L13 (-20, 31.95) -> (-20, 30)
  line L14 (-21.45, 32.55) -> (-18.55, 32.55)
  line L15 (-21.45, 31.35) -> (-21.45, 32.55)
  line L16 (-18.55, 31.35) -> (-21.45, 31.35)
  line L17 (-18.55, 32.55) -> (-18.55, 31.35)
  line L18 (-21.45, 31.35) -> (-18.55, 32.55)
  line L19 (-18.55, 31.35) -> (-21.45, 32.55)
  line L20 (-20, 15) -> (-20, 45)
  line L21 (-25, 30) -> (-15, 30)
  line L22 (-25, 39.1) -> (-15, 39.1)
  line L23 (-25, 20.9) -> (-15, 20.9)
  line L24 (-23.35, 15) -> (-23.35, 45)
  line L25 (-16.65, 15) -> (-16.65, 45)
  line L26 (-25, 42.6) -> (-15, 42.6)
  line L27 (-25, 15.2) -> (-15, 15.2)
  line L28 (-23.9, 15) -> (-23.9, 45)
  line L29 (-16.1, 15) -> (-16.1, 45)
  line L30 (-25, 16.6) -> (-15, 16.6)
  line L31 (-22.6, 15.2) -> (-17.4, 15.2)
  line L32 (-22.6, 18) -> (-22.6, 15.2)
  line L33 (-17.4, 18) -> (-22.6, 18)
  line L34 (-17.4, 15.2) -> (-17.4, 18)
  line L35 (-22.6, 18) -> (-17.4, 15.2)
  line L36 (-17.4, 18) -> (-22.6, 15.2)
  line L37 (-18.5, 16.35) -> (-21.5, 16.35)
  line L38 (-21.5, 16.85) -> (-18.5, 16.85)
  line L39 (-18.5, 16.6) -> (-21.5, 16.6)
  circle C1 centre (-20, 39.1) radius 2.325
  circle C2 centre (-20, 20.9) radius 2.325
  arc A1 centre (-18.5, 16.6) radius 0.25 clockwise from (-18.5, 16.85) to (-18.5, 16.35)
  arc A2 centre (-21.5, 16.6) radius 0.25 clockwise from (-21.5, 16.35) to (-21.5, 16.85)
  circle C3 centre (-20, 20.9) radius 3.9
  point P6 (-20, 30)
  point P11 (-20, 30)
  point P12 (-20, 30)
  point P18 (-20, 31.95)
  point P13 (-20, 31.95)
  point P19 (-20, 39.1)
  point P20 (-20, 20.9)
  point P47 (-20, 16.6)
  point P54 (-20, 16.6)
  point P4 (-22.9, 23.6)
  point P5 (-17.1, 23.6)
  point P3 (-22.9, 36.4)
  point P9 (-20.2, 35.53)
  point P10 (-19.8, 35.53)
  point P8 (-20.2, 24.47)
  point P16 (-21.45, 31.35)
  point P17 (-18.55, 31.35)
  point P15 (-21.45, 32.55)
  point P45 (-22.6, 18)
  point P46 (-17.4, 18)
  point P44 (-22.6, 15.2)
  horizontal L1
  perpendicular L1 L2
  parallel L1 L3
  parallel L2 L4
  coincident L5 P6
  coincident L6 P6
  horizontal L7
  perpendicular L7 L8
  parallel L7 L9
  parallel L8 L10
  coincident L11 P11
  coincident L12 P11
  coincident P6 P11
  coincident P11 P12
  perpendicular L1 L13
  horizontal L14
  perpendicular L14 L15
  parallel L14 L16
  parallel L15 L17
  coincident L18 P18
  coincident L19 P18
  coincident P13 P18
  perpendicular L16 L20
  midpoint P6 L20
  perpendicular L2 L21
  midpoint P11 L21
  coincident P19 L20
  coincident P19 L22
  coincident P20 L20
  coincident P20 L23
  horizontal L31
  perpendicular L31 L32
  parallel L31 L33
  parallel L32 L34
  coincident L35 P47
  coincident L36 P47
  midpoint L30 P47
  tangent L37 A1
  tangent A1 L38
  parallel L37 L38
  tangent L38 A2
  tangent L37 A2
  parallel L30 L39
  coincident P47 P54
  midpoint L39 P54
  concentric C2 C3
  tangent L29 C3
  dimension "d448" distance P4 P5 = 5.8
  dimension "d449" distance P3 P4 = 12.8
  dimension "d450" distance P9 P10 = 0.4
  dimension "d451" distance P8 P9 = 11.06
  dimension "d452" distance P12 P13 = 1.95
  dimension "d453" distance P16 P17 = 2.9
  dimension "d454" distance P15 P16 = 1.2
  dimension "d456" diameter C1 = 4.65
  dimension "d457" diameter C2 = 4.65
  dimension "d458" = 9.1
  dimension "d459" = -9.1
  dimension "d460" = 3.35
  dimension "d461" = -3.35
  dimension "d462" = 12.6
  dimension "d463" = -14.8
  dimension "d464" = 3.9
  dimension "d465" = -3.9
  dimension "d466" = -13.4
  dimension "d467" distance P45 P46 = 5.2
  dimension "d468" distance P44 P45 = 2.8
  dimension "d469" diameter A1 = 0.5
extrude "押し出し1" new body sketch "スケッチ1" profile of L1 L2 L3 L4 L7 L8 L9 L10 L13 L14 L15 L16 L17 C1 C2 L20 L21 L22 L23 L24 L25 L26 L27 L28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 blind -0.8 from offset 7.4 bodies "pcb"
extrude "押し出し2" sketch "スケッチ1" profile of L1 L2 L3 L4 L7 L8 L9 L10 L13 L14 L15 L16 L17 L20 L21 blind 6.5 bodies "switch"
extrude "押し出し3" sketch "スケッチ1" profile of L8 L10 L13 L14 L15 L16 L17 L20 blind 0.85
extrude "押し出し4" sketch "スケッチ1" profile of L7 L8 L9 L10 L13 L14 L16 L20 L21 blind -3.2
extrude "押し出し5" sketch "スケッチ1" profile of L20 L27 L30 L31 L32 L33 L34 L37 A1 L38 A2 blind -5 bodies "conn"
extrude "押し出し6" sketch "スケッチ1" profile of L20 L30 L37 A1 L38 A2 blind 2.5
sketch "スケッチ1" plane through (0, 0, 0) normal (1, 0, 0) x axis (0, 1, 0)
  line L1 (-25, 0) -> (25, 0)
  line L2 (-25, 7.4) -> (25, 7.4)
  line L3 (-25, 7.9) -> (25, 7.9)
  line L4 (-25, 19.8) -> (25, 19.8)
  line L5 (-25, 14.8) -> (25, 14.8)
  line L6 (0, 25) -> (0, 0)
  line L7 (-4.1, 25) -> (-4.1, 0)
  line L8 (13.2, 25) -> (13.2, 0)
  line L9 (14.3, 24.9) -> (14.3, -0.1)
  line L10 (4.3, 25) -> (4.3, 0)
  line L11 (-25, 10.9) -> (25, 10.9)
  line L12 (-20, 25) -> (-20, 0)
  line L13 (-17.6, 25) -> (-17.6, 0)
  line L14 (-20, 17.8) -> (-18, 19.8)
  line L15 (14.3, 12.8) -> (12.3, 14.8)
  line L16 (-25, 10.5) -> (25, 10.5)
  line L17 (-25, 11.8) -> (25, 11.8)
  point P1 (0, 0)
  point P12 (0, 0)
  point P28 (-18, 19.8)
  point P29 (-20, 17.8)
  point P30 (12.3, 14.8)
  point P31 (14.3, 12.8)
  horizontal L1
  coincident P1 P12
  perpendicular L4 L6
  coincident L4 P28
  coincident L12 P29
  coincident L5 P30
  coincident L9 P31
  dimension "d507" = 7.4
  dimension "d508" = 0.5
  dimension "d509" = 12.4
  dimension "d510" = 7.4
  dimension "d511" = -4.1
  dimension "d512" = 13.2
  dimension "d513" = 14.3
  dimension "d514" = 4.3
  dimension "d515" = 3.5
  dimension "d516" = -20
  dimension "d517" = -17.6
  dimension "d523" distance L12 P28 = 2
  dimension "d524" distance L4 P29 = 2
  dimension "d525" distance L9 P30 = 2
  dimension "d526" distance L5 P31 = 2
  dimension "d527" = 3.1
  dimension "d528" = 4.4
extrude "押し出し1" new body sketch "スケッチ1" profile of L2 L3 L4 L5 L6 L7 L8 L9 L10 L11 L12 L13 L14 L15 L16 L17 blind -1.2 from offset -16 bodies "pcb"
sketch "スケッチ2" plane through (0, 0, 0) normal (1, 0, 0) x axis (0, 1, 0)
  line L1 (-25, 0) -> (25, 0)
  line L2 (0, 25) -> (0, 0)
  line L3 (-25.1, 7.4) -> (24.9, 7.4)
  line L4 (-25.1, 11) -> (24.9, 11)
  line L5 (6.8, 25) -> (6.8, 0)
  line L6 (13.2, 8.1) -> (0.4, 8.1)
  line L7 (13.2, 13.9) -> (13.2, 8.1)
  line L8 (0.4, 13.9) -> (13.2, 13.9)
  line L9 (0.4, 8.1) -> (0.4, 13.9)
  line L10 (13.2, 13.9) -> (0.4, 8.1)
  line L11 (0.4, 13.9) -> (13.2, 8.1)
  line L12 (12.33, 10.8) -> (1.27, 10.8)
  line L13 (12.33, 11.2) -> (12.33, 10.8)
  line L14 (1.27, 11.2) -> (12.33, 11.2)
  line L15 (1.27, 10.8) -> (1.27, 11.2)
  line L16 (12.33, 11.2) -> (1.27, 10.8)
  line L17 (1.27, 11.2) -> (12.33, 10.8)
  line L18 (8.75, 11) -> (6.8, 11)
  line L19 (9.35, 9.55) -> (8.15, 9.55)
  line L20 (9.35, 12.45) -> (9.35, 9.55)
  line L21 (8.15, 12.45) -> (9.35, 12.45)
  line L22 (8.15, 9.55) -> (8.15, 12.45)
  line L23 (9.35, 12.45) -> (8.15, 9.55)
  line L24 (8.15, 12.45) -> (9.35, 9.55)
  line L25 (-5.57, 14.5) -> (-16.63, 14.1)
  line L26 (-16.63, 14.1) -> (-16.63, 14.5)
  line L27 (-9.75, 15.75) -> (-8.55, 12.85)
  line L28 (-16.63, 14.5) -> (-5.57, 14.5)
  line L29 (-9.75, 15.75) -> (-8.55, 15.75)
  line L30 (-9.75, 12.85) -> (-9.75, 15.75)
  line L31 (-17.5, 17.2) -> (-4.7, 17.2)
  line L32 (-4.7, 17.2) -> (-4.7, 11.4)
  line L33 (-8.55, 15.75) -> (-8.55, 12.85)
  line L34 (-8.55, 15.75) -> (-9.75, 12.85)
  line L35 (-17.5, 17.2) -> (-4.7, 11.4)
  line L36 (-9.15, 14.3) -> (-11.1, 14.3)
  line L37 (-8.55, 12.85) -> (-9.75, 12.85)
  line L38 (-5.57, 14.1) -> (-16.63, 14.1)
  line L39 (-5.57, 14.5) -> (-5.57, 14.1)
  line L40 (-16.63, 14.5) -> (-5.57, 14.1)
  line L41 (-4.7, 17.2) -> (-17.5, 11.4)
  line L42 (-17.5, 11.4) -> (-17.5, 17.2)
  line L43 (-4.7, 11.4) -> (-17.5, 11.4)
  line L44 (-25.1, 14.3) -> (24.9, 14.3)
  line L45 (-11.1, 25) -> (-11.1, 0)
  line L46 (-25.1, 9) -> (24.9, 9)
  line L47 (-7.6, 8) -> (-14.6, 8)
  line L48 (-7.6, 10) -> (-7.6, 8)
  line L49 (-14.6, 10) -> (-7.6, 10)
  line L50 (-14.6, 8) -> (-14.6, 10)
  line L51 (-7.6, 10) -> (-14.6, 8)
  line L52 (-14.6, 10) -> (-7.6, 8)
  point P1 (0, 0)
  point P4 (0, 0)
  point P16 (6.8, 11)
  point P21 (6.8, 11)
  point P22 (6.8, 11)
  point P28 (8.75, 11)
  point P23 (8.75, 11)
  point P43 (-11.1, 14.3)
  point P45 (-11.1, 14.3)
  point P44 (-11.1, 14.3)
  point P42 (-9.15, 14.3)
  point P35 (-9.15, 14.3)
  point P56 (-11.1, 9)
  point P14 (13.2, 13.9)
  point P15 (0.4, 13.9)
  point P13 (13.2, 8.1)
  point P19 (12.33, 11.2)
  point P20 (1.27, 11.2)
  point P18 (12.33, 10.8)
  point P26 (9.35, 12.45)
  point P27 (8.15, 12.45)
  point P25 (9.35, 9.55)
  point P38 (-4.7, 17.2)
  point P39 (-17.5, 17.2)
  point P37 (-4.7, 11.4)
  point P29 (-5.57, 14.5)
  point P30 (-16.63, 14.5)
  point P32 (-5.57, 14.1)
  point P40 (-9.75, 15.75)
  point P41 (-8.55, 15.75)
  point P33 (-8.55, 12.85)
  point P54 (-7.6, 10)
  point P55 (-14.6, 10)
  point P53 (-7.6, 8)
  horizontal L1
  coincident P1 P4
  perpendicular L1 L2
  horizontal L6
  perpendicular L6 L7
  parallel L6 L8
  parallel L7 L9
  coincident L10 P16
  coincident L11 P16
  horizontal L12
  perpendicular L12 L13
  parallel L12 L14
  parallel L13 L15
  coincident L16 P21
  coincident L17 P21
  coincident P16 P21
  coincident P21 P22
  perpendicular L7 L18
  horizontal L19
  perpendicular L19 L20
  parallel L19 L21
  parallel L20 L22
  coincident L23 P28
  coincident L24 P28
  coincident P23 P28
  horizontal L43
  perpendicular L32 L43
  parallel L31 L43
  parallel L32 L42
  coincident P43 L41
  coincident P43 L35
  horizontal L38
  perpendicular L38 L39
  parallel L28 L38
  parallel L26 L39
  coincident P45 L25
  coincident P45 L40
  coincident P43 P45
  coincident P44 P45
  perpendicular L32 L36
  horizontal L37
  perpendicular L33 L37
  parallel L29 L37
  parallel L30 L33
  coincident P42 L34
  coincident P42 L27
  coincident P35 P42
  coincident L4 P16
  coincident L5 P16
  coincident P45 L45
  coincident P43 L44
  horizontal L47
  perpendicular L47 L48
  parallel L47 L49
  parallel L48 L50
  coincident L51 P56
  coincident L52 P56
  coincident L45 P56
  coincident L46 P56
  dimension "d537" = 7.4
  dimension "d538" = 3.6
  dimension "d539" = 6.8
  dimension "d540" distance P14 P15 = 12.8
  dimension "d541" distance P13 P14 = 5.8
  dimension "d542" distance P19 P20 = 11.06
  dimension "d543" distance P18 P19 = 0.4
  dimension "d544" distance P22 P23 = 1.95
  dimension "d545" distance P26 P27 = 1.2
  dimension "d546" distance P25 P26 = 2.9
  dimension "d547" distance P38 P39 = 12.8
  dimension "d548" distance P37 P38 = 5.8
  dimension "d549" distance P29 P30 = 11.06
  dimension "d550" distance P29 P32 = 0.4
  dimension "d551" distance P35 P44 = 1.95
  dimension "d552" distance P40 P41 = 1.2
  dimension "d553" distance P33 P41 = 2.9
  dimension "d554" = 6.9
  dimension "d555" = -11.1
  dimension "d556" = 1.6
  dimension "d557" distance P54 P55 = 7
  dimension "d558" distance P53 P54 = 2
extrude "押し出し3" sketch "スケッチ2" profile of L4 L5 L6 L7 L8 L9 L12 L13 L14 L15 L18 L19 L20 L21 L22 L26 L28 L29 L30 L31 L32 L33 L36 L37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 blind -6.5 bodies "switch5", "switch4"
extrude "押し出し4" sketch "スケッチ2" profile of L4 L12 L14 L18 L19 L20 L21 L22 L28 L29 L30 L33 L36 L37 L38 L44 blind -0.85
extrude "押し出し5" sketch "スケッチ2" profile of L4 L5 L12 L13 L14 L15 L18 L20 L22 L26 L28 L30 L33 L36 L38 L39 L44 L45 blind 3.2
extrude "押し出し6" sketch "スケッチ2" profile of L45 L46 L47 L48 L49 L50 blind 2.4 second side blind 1.2
sketch "スケッチ1" plane through (0, 0, 0) normal (0, 1, 0) x axis (1, 0, 0)
  line L1 (-10, 0) -> (10, 0)
  line L2 (-10, -7.4) -> (10, -7.4)
  line L3 (0, -15) -> (0, 0)
  line L4 (-10, -0.9) -> (10, -0.9)
  line L5 (-10, -4.9) -> (10, -4.9)
  line L6 (-4.9, -15) -> (-4.9, 0)
  line L7 (4.9, -15) -> (4.9, 0)
  line L8 (-2.5, -15) -> (-2.5, 0)
  line L9 (2.5, -15) -> (2.5, 0)
  line L10 (-7.4, -15) -> (-7.4, 0)
  line L11 (7.4, -15) -> (7.4, 0)
  line L12 (-5.6, -15) -> (-5.6, 0)
  line L13 (5.6, -15) -> (5.6, 0)
  circle C1 centre (0, -4.15) radius 3.25
  circle C2 centre (0, -4.15) radius 1.25
  point P1 (0, 0)
  point P6 (0, 0)
  horizontal L1
  coincident P1 P6
  perpendicular L2 L3
  tangent L4 C1
  concentric C1 C2
  dimension "d582" = -7.4
  dimension "d583" = 6.5
  dimension "d584" = -4
  dimension "d585" = 4.9
  dimension "d586" = -4.9
  dimension "d587" = 2.5
  dimension "d588" = -2.5
  dimension "d595" = 7.4
  dimension "d596" = -7.4
  dimension "d600" diameter C2 = 2.5
  dimension "d951" = 5.6
  dimension "d952" = -5.6 (= "-d951")
extrude "押し出し1" new body sketch "スケッチ1" profile of L2 L3 L4 L5 L6 L7 L8 L9 C1 L10 L11 C2 L12 L13 blind 6 from offset 46
extrude "押し出し2" sketch "スケッチ1" profile of L2 L3 L4 L5 L8 L9 C1 C2 blind -1.5
extrude "押し出し3" sketch "スケッチ1" profile of L2 L3 L4 L5 L6 L7 L8 L9 C1 blind -2
extrude "押し出し4" sketch "スケッチ1" profile of L3 L5 C2 blind -2.5
extrude "押し出し5" sketch "スケッチ1" profile of L3 L5 L8 L9 C1 C2 blind 5
chamfer "面取り1" distance 6.5 Rotate Angle 30
fillet "フィレット1" radius 1 2.5
position "位置"
mirror_component "コンポーネントをミラー化"
derived_instance "DerivedInstance4"
base_mesh_feature "基準メッシュ フィーチャ1"
step "メッシュを削減" Proportion 25
base_mesh_feature "基準メッシュ フィーチャ2"
modify "修正1"
modify "修正2"
sketch "スケッチ5" plane through (0, 0, 0) normal (0, 0, 1) x axis (1, 0, 0)
  line L1 (173.2753, 159.366) -> (-170.9716, 159.366)
  line L2 (173.2753, -175.5114) -> (173.2753, 159.366)
  line L3 (-170.9716, -175.5114) -> (173.2753, -175.5114)
  line L4 (-170.9716, 159.366) -> (-170.9716, -175.5114)
  horizontal L1
  vertical L2
  horizontal L3
  vertical L4
sketch "スケッチ43" plane through (0, 0, 0) normal (1, 0, 0) x axis (0, 1, 0)
  line L1 (70, 0) -> (-69, 0)
  horizontal L1
form "フォーム" bodies "surface"
move "移動7"
copy_paste_bodies "ボディのコピーと貼り付け6"
move "移動8"
surface_patch "サーフェス パッチ1" bodies "surface_mid"
surface_patch "サーフェス パッチ2" bodies "surface_bot"
split "分割1" bodies "surface_1"
copy_paste_bodies "ボディのコピーと貼り付け7"
move "移動9"
step "サーフェス延長" extendDistance 5
step "サーフェス オフセット1" offset -1.2 bodies "surface_1_ext_1.2mm"
step "サーフェス オフセット5" offset -0.6 bodies "surface_1_ext_0.6mm"
step "サーフェス オフセット6" offset -2.5 bodies "surface_1_ext_2.5mm"
copy_paste_bodies "ボディのコピーと貼り付け13"
move "移動15"
step "サーフェス オフセット3" offset -1.5 bodies "surface_2_ext_1.5mm"
extrude "押し出し100" new body sketch "スケッチ5" along normal blind 50 bodies "box"
copy_paste_bodies "ボディのコピーと貼り付け18"
move "移動20"
split "分割22" bodies "box_surface_out"
copy_paste_bodies "ボディのコピーと貼り付け8"
move "移動10"
split "分割5" bodies "box_1_out"
split "分割6" bodies "box_1_0-1.2mm"
copy_paste_bodies "ボディのコピーと貼り付け21"
move "移動23"
split "分割29" bodies "box_1_0-0.6mm"
copy_paste_bodies "ボディのコピーと貼り付け23"
move "移動25"
split "分割32" bodies "box_1_0-2.5mm"
copy_paste_bodies "ボディのコピーと貼り付け14"
move "移動16"
extrude "押し出し101" cut of existing geometry blind -30
split "分割7" bodies "box_2_out"
split "分割8" bodies "box_2_0-1.5mm"
extrude "押し出し154" new body sketch "スケッチ5" along normal blind 2 bodies "box_bot_2mm_in"
split "分割20" bodies "box_bot_2mm_out"
copy_paste_bodies "ボディのコピーと貼り付け17"
move "移動19"
combine "結合41" bodies "box_2_0-1.5mm (1)"
combine "結合42"
sketch "スケッチ57" plane through (0, 35.7957, -20.5667) normal (0, 0.866, -0.5) x axis (-1, 0, 0)
  line L1 (5.6, 29.5218) -> (6.4, 29.5218)
  line L2 (0, 32.4086) -> (3.1, 32.4086)
  line L3 (7.4, 24.903) -> (0, 24.903)
  line L4 (7.4, 28.3671) -> (7.4, 24.903)
  line L5 (50.368, 41.0656) -> (-49.6774, 41.0656)
  line L6 (50.368, 16.6656) -> (50.368, 41.0656)
  line L7 (-49.6774, 16.6656) -> (50.368, 16.6656)
  line L8 (-49.6774, 41.0656) -> (-49.6774, 16.6656)
  closed curve K1 centre (6.4, 28.3671)
  closed curve K2 centre (0, 28.6558)
  closed curve K3 centre (3.1, 29.5218)
  horizontal L5
  vertical L6
  horizontal L7
  vertical L8
extrude "押し出し102" new body sketch "スケッチ57" profile of K1 L1 L2 K2 L3 L4 L5 L6 L7 L8 against normal blind 1.5
extrude "押し出し155" cut sketch "スケッチ5" against normal blind 30.583
extrude "押し出し156" cut of existing geometry blind -24.127
combine "結合43"
sketch "スケッチ58" plane through (0, 0, 0) normal (0, 1, 0) x axis (1, 0, 0)
  line L1 (-5.6, -5) -> (-6.4, -5)
  line L2 (0, -7.5) -> (-3.1, -7.5)
  line L3 (-7.4, -1) -> (0, -1)
  line L4 (-7.4, -4) -> (-7.4, -1)
  line L5 (7.4, -1) -> (7.4, -4)
  line L6 (0, -1) -> (7.4, -1)
  line L7 (3.1, -7.5) -> (0, -7.5)
  line L8 (6.4, -5) -> (5.6, -5)
  line L9 (-4.9, -7.5) -> (4.9, -7.5)
  line L10 (-4.9, -1) -> (-4.9, -7.5)
  line L11 (4.9, -1) -> (-4.9, -1)
  line L12 (4.9, -7.5) -> (4.9, -1)
  line L13 (2.5, -7.5) -> (2.5, -1)
  line L14 (4.9, -7.5) -> (2.5, -7.5)
  line L15 (4.9, -1) -> (4.9, -7.5)
  line L16 (2.5, -1) -> (4.9, -1)
  line L17 (-2.5, -1) -> (-2.5, -7.5)
  line L18 (-4.9, -1) -> (-2.5, -1)
  line L19 (-4.9, -7.5) -> (-4.9, -1)
  line L20 (-2.5, -7.5) -> (-4.9, -7.5)
  line L21 (6.1, 0.2) -> (-6.1, 0.2)
  line L22 (6.1, -8.7) -> (6.1, 0.2)
  line L23 (-6.1, -8.7) -> (6.1, -8.7)
  line L24 (-6.1, 0.2) -> (-6.1, -8.7)
  line L25 (3.1, -11.87) -> (3.1, -7.5)
  line L26 (-2.5, -9.5343) -> (-2.5, -7.5)
  line L27 (7.4, 2) -> (7.4, -1)
  line L28 (4.9, 1.6875) -> (4.9, -1)
  line L29 (-7.4, 2.635) -> (-7.4, -1)
  line L30 (-4.9, 2.6051) -> (-4.9, -1)
  line L31 (2.5, 1.5027) -> (2.5, -1)
  line L32 (-2.5, 1.7097) -> (-2.5, -1)
  line L33 (15, 0) -> (-15, 0)
  line L34 (-8.6, 0.2) -> (0, 0.2)
  line L35 (-8.6, -4) -> (-8.6, 0.2)
  line L36 (0, -8.7) -> (-3.1, -8.7)
  line L37 (3.1, -8.7) -> (0, -8.7)
  line L38 (8.6, 0.2) -> (8.6, -4)
  line L39 (0, 0.2) -> (8.6, 0.2)
  arc A1 centre (-6.4, -4) radius 1 clockwise from (-6.4, -5) to (-7.4, -4)
  arc A2 centre (6.4, -4) radius 1 clockwise from (7.4, -4) to (6.4, -5)
  circle C1 centre (0, -4.25) radius 1.25
  arc A3 centre (4.9, -7.5) radius 1.2 clockwise from (6.1, -7.5) to (4.9, -8.7)
  arc A4 centre (-4.9, -7.5) radius 1.2 clockwise from (-4.8975, -8.7) to (-6.1, -7.5025)
  arc A5 centre (-3.1, -5) radius 2.5 clockwise from (-3.1, -7.5) to (-5.6, -5)
  arc A6 centre (3.1, -5) radius 2.5 clockwise from (5.6, -5) to (3.1, -7.5)
  arc A7 centre (-6.4, -4) radius 2.2 clockwise from (-6.6032, -6.1906) to (-8.6, -4)
  arc A8 centre (-3.1, -5) radius 3.7 clockwise from (-3.1, -8.7) to (-6.6032, -6.1906)
  arc A9 centre (3.1, -5) radius 3.7 clockwise from (6.6032, -6.1906) to (3.1, -8.7)
  arc A10 centre (6.4, -4) radius 2.2 clockwise from (8.6, -4) to (6.6032, -6.1906)
  point P16 (3.1, -7.5)
  point P35 (3.1, -7.5)
  point P27 (-2.5, -7.5)
  point P37 (-2.5, -7.5)
  point P13 (7.4, -1)
  point P39 (7.4, -1)
  point P22 (4.9, -1)
  point P41 (4.9, -1)
  point P9 (-7.4, -1)
  point P43 (-7.4, -1)
  point P21 (-4.9, -1)
  point P45 (-4.9, -1)
  point P23 (2.5, -1)
  point P47 (2.5, -1)
  point P28 (-2.5, -1)
  point P49 (-2.5, -1)
  point P55 (6.1, -7.5)
  point P54 (4.9, -8.7)
  point P19 (4.9, -7.5)
  point P53 (4.9, -7.5)
  point P57 (-6.1, -7.5025)
  point P58 (-4.8975, -8.7)
  point P30 (-4.9, -7.5)
  point P56 (-4.9, -7.5)
  coincident P16 P35
  perpendicular L23 L25
  coincident P27 P37
  coincident P13 P39
  coincident P22 P41
  coincident P9 P43
  coincident P21 P45
  coincident P23 P47
  perpendicular L21 L31
  coincident P28 P49
  perpendicular L27 L33
  coincident L22 P55
  coincident L23 P54
  coincident P19 P53
  coincident L24 P57
  coincident L23 P58
  coincident P30 P56
  dimension "d643" = -1.2
  dimension "d957" = 1.2
extrude "押し出し157" cut sketch "スケッチ58" profile of A1 L1 L2 L3 L4 A2 L5 L6 L7 L8 C1 L9 L10 L11 L12 L13 L14 L15 L16 L17 L18 L19 L20 L21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 along normal blind 61.4627
extrude "押し出し158" sketch "スケッチ58" profile of A1 L1 L2 L3 L4 A2 L5 L6 L7 L8 C1 L9 L10 L11 L12 L13 L14 L15 L16 L17 L18 L19 L20 L22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 to an object from offset 1 bodies "bush_mawari"
extrude "押し出し160" sketch "スケッチ58" profile of L1 L2 L3 L6 L7 L8 L9 L10 L12 L14 L15 L19 L20 L22 L23 L24 L25 A3 A4 A5 A6 A8 L36 L37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 to an object offset 1
extrude "押し出し161" sketch "スケッチ58" profile of L2 L3 L6 L7 L9 L10 L11 L12 L13 L14 L15 L16 L17 L18 L19 L20 A5 A6 to an object
combine "結合46"
combine "結合47"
